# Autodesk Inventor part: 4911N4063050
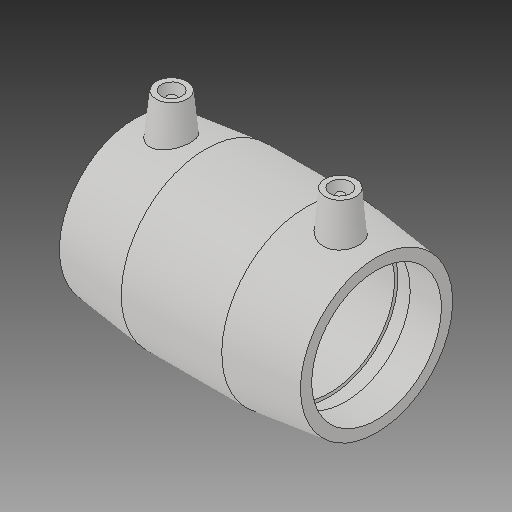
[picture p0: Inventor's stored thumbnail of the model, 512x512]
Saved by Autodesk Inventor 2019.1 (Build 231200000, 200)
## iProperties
Created: 2017-06
Part Number: 4911N4063050
Material: Generic
Description: PLASSON ASTM REDUCING COUPLING ADAPTOR 63-2''
Document SubType Name: Modeling
Designer: KIM
Mass: 54.8237 g
Surface Area: 155.252 cm^2
Volume: 54.8237 cm^3
Density: 1 g/cm^3
Appearance: Default
Author: KIM
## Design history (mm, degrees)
derived "4911N.ipt"
feature "Solid1::4911N.ipt"
tag "TaggingFeature1"
body "Solid1"
other parameters: "d0" = 117.094, "d2" = 82.042, "d3" = 56.896, "d4" = 34.1376, "d5" = 73.8378, "d7" = 60.1, "d8" = 168 deg, "d10" = 22.7584, "d11" = 7.58613, "d14" = 17.6296, "d22" = 108.92847, "d29" = 57.404, "d30" = 15, "d31" = 40.9829, "d34" = 6 deg, "d41" = 4, "d42" = 14, "d43" = 0, "d48" = 82.042, "d49" = 63, "d50" = 82.042, "d52" = 54.09, "d53" = 22.7584, "d54" = 7.58613, "d55" = 168 deg, "d56" = 34.1376, "d57" = 56.896, "d58" = 73.8378, "d59" = 2.8448, "d60" = 135 deg, "d61" = 57.404, "d62" = 15, "d64" = 4, "d66" = 5 deg, "d67" = 14, "d68" = 0, "d69" = 40.9829, "d95" = 3, "d96" = 0, "d97" = 3, "d98" = 0, "d_1" = 60.1, "L_" = 117.094, "L_2" = 56.896, "D_1" = 82.042, "A_1" = 57.404, "d_2" = 12, "L_1" = 56.896, "d_" = 63, "A_" = 57.404, "D_" = 82.042
